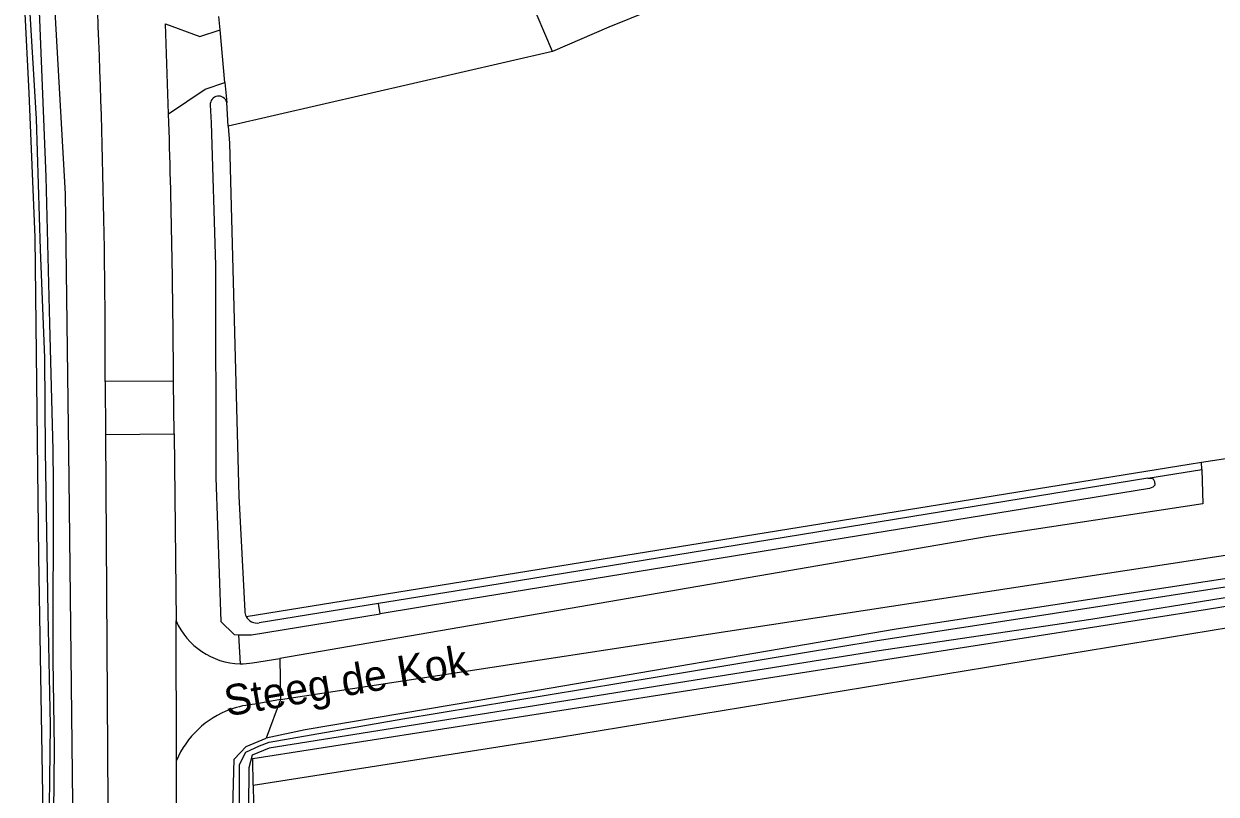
# Model space of a CAD drawing. Extents: x 134297 to 137000, y 403500 to 406000.
# Drawn here: x 135047 to 135144.1, y 403677.8 to 403740.5 of the extents above; entities that cross this region are included whole.
import ezdxf

# ---------------------------------------------------------------- set-up
doc = ezdxf.new("R2010")
doc.units = 0
for name, color, linetype in [('gg-anno-openbare ruimte label', 7, 'Continuous'), ('gg-kntw-bovenkant insteek waterloop', 7, 'Continuous'), ('gg-kntw-waterlijn', 7, 'Continuous'), ('gx-grn-maaiveld', 7, 'Continuous')]:
    doc.layers.add(name, color=color, linetype=linetype)

msp = doc.modelspace()

# ---------------------------------------------------------------- linework, layer by layer
at = {"layer": 'gg-kntw-bovenkant insteek waterloop'}
for points in [[(135171.746, 403699.428), (135118.043, 403691.21), (135085.627, 403685.656), (135069.863, 403683.006), (135066.699, 403682.331)], [(135065.623, 403680.671), (135143.41, 403692.842), (135171.876, 403697.442)]]:
    msp.add_lwpolyline(points, dxfattribs=at)
at = {"layer": 'gg-kntw-waterlijn'}
msp.add_lwpolyline([(135066.934, 403681.993), (135077.838, 403683.899), (135116.331, 403690.244), (135169.319, 403698.436), (135208.319, 403704.818), (135208.686, 403704.046), (135133.896, 403691.995), (135116.465, 403689.408), (135077.663, 403683.211), (135066.933, 403681.511), (135065.545, 403680.928), (135065.288, 403679.91), (135065.185, 403666.72), (135065.306, 403647.731), (135064.91, 403647.731), (135064.537, 403667.991), (135064.537, 403680.178), (135065.038, 403681.176), (135066.154, 403681.705), (135066.934, 403681.993)], dxfattribs=at)
at = {"layer": 'gx-grn-maaiveld'}
for p, q in [((135090.022, 403738.28), (135085.548, 403748.763)), ((135058.749, 403733.177), (135058.487, 403740.522)), ((135062.945, 403740.034), (135062.847, 403741.108)), ((135063.339, 403735.739), (135062.945, 403740.034)), ((135090.022, 403738.28), (135063.611, 403732.174)), ((135063.339, 403735.739), (135063.488, 403734.119)), ((135063.611, 403732.174), (135063.488, 403734.119)), ((135059.15, 403711.396), (135053.591, 403711.368)), ((135053.617, 403707.066), (135059.194, 403707.108)), ((135059.194, 403707.108), (135059.353, 403691.887)), ((135142.922, 403704.807), (135145.947, 403705.283)), ((135142.938, 403704.217), (135142.922, 403704.807)), ((135138.542, 403703.503), (135082.11, 403694.309)), ((135138.542, 403703.503), (135142.938, 403704.217)), ((135067.861, 403685.46), (135171.62, 403701.339)), ((135082.11, 403694.309), (135075.848, 403693.289)), ((135075.848, 403693.289), (135066.119, 403691.704)), ((135075.984, 403692.453), (135075.848, 403693.289)), ((135059.382, 403680.509), (135059.353, 403691.887)), ((135064.454, 403690.751), (135064.573, 403688.384)), ((135065.591, 403688.45), (135067.823, 403688.816)), ((135067.823, 403688.816), (135067.861, 403685.46)), ((135067.861, 403685.46), (135065.805, 403685.094)), ((135067.861, 403685.46), (135066.699, 403682.331)), ((135059.461, 403650.158), (135059.382, 403680.509)), ((135065.642, 403678.482), (135065.623, 403680.671)), ((135065.642, 403678.482), (135065.655, 403677.033))]:
    msp.add_line(p, q, dxfattribs=at)
for points in [[(135117.256, 403749.391), (135094.612, 403740.24), (135090.022, 403738.28)], [(135048.269, 403661.402), (135048.508, 403662.925), (135048.642, 403669.65), (135048.181, 403697.127), (135047.874, 403723.105), (135047.374, 403734.903), (135046.951, 403743.53)], [(135049.344, 403743.941), (135050.32, 403726.679), (135050.621, 403703.438), (135051.004, 403669.814), (135050.927, 403662.756), (135050.536, 403661.631), (135049.892, 403661.131), (135049.321, 403661.012), (135048.538, 403661.138), (135048.269, 403661.402)], [(135048.974, 403672.412), (135049.127, 403683.365), (135048.935, 403692.511), (135048.705, 403705.73), (135048.666, 403713.301), (135048.32, 403722.14), (135047.975, 403732.784), (135047.398, 403742.757), (135047.475, 403743.083), (135047.782, 403743.237), (135048.071, 403743.18), (135048.148, 403742.911), (135048.743, 403728.058), (135049.051, 403716.106), (135049.32, 403705.807), (135049.339, 403703.136), (135049.32, 403688.706)], [(135058.487, 403740.522), (135061.296, 403739.486), (135062.945, 403740.034)], [(135058.749, 403733.177), (135061.732, 403735.205), (135063.339, 403735.739)], [(135062.141, 403733.915), (135062.226, 403732.456), (135062.57, 403720.837), (135062.582, 403703.55), (135063.013, 403691.824), (135064.092, 403690.754), (135064.454, 403690.751)], [(135063.611, 403732.174), (135063.697, 403730.812), (135064.459, 403702.032), (135064.958, 403692.663)], [(135053.591, 403711.368), (135053.591, 403711.364), (135053.591, 403711.361), (135053.617, 403707.066)], [(135059.194, 403707.108), (135059.15, 403711.339), (135059.15, 403711.367), (135059.15, 403711.396)], [(135053.617, 403707.066), (135053.879, 403664.105), (135053.891, 403662.086)], [(135065.069, 403692.232), (135141.918, 403704.649), (135142.922, 403704.807)], [(135065.642, 403678.482), (135090.588, 403682.403), (135213.204, 403702.49), (135212.883, 403704.352)], [(135142.938, 403704.217), (135143.016, 403701.424), (135125.52, 403698.762), (135067.823, 403688.816)], [(135138.542, 403703.503), (135138.812, 403703.505), (135138.982, 403703.451), (135139.091, 403703.242), (135139.098, 403702.935), (135138.947, 403702.775), (135138.678, 403702.667), (135082.246, 403693.473), (135075.984, 403692.453)], [(135064.454, 403690.751), (135065.493, 403690.744), (135075.984, 403692.453)], [(135049.32, 403688.706), (135049.416, 403681.501), (135049.32, 403670.952)], [(135063.771, 403667.214), (135063.964, 403675.584), (135064.08, 403680.621), (135065.055, 403681.64), (135066.699, 403682.331)]]:
    msp.add_lwpolyline(points, dxfattribs=at)
for centre, radius, start, end in [((134325.105, 403711.44), 728.486, 359.994312, 3.032345), ((135062.824, 403733.952), 0.684, 14.09246, 183.13127), ((134217.873, 403706.802), 841.289, 0.312886, 1.796568), ((135064.704, 403694.22), 5.838, 203.55879, 268.71224), ((135065.947, 403692.688), 0.99, 181.4459, 207.43839), ((135065.958, 403692.693), 1.002, 207.37845, 279.22982), ((135064.7, 403694.302), 5.919, 268.76585, 278.65308), ((135066.391, 403677.498), 7.618, 94.41084, 110.09059), ((135066.401, 403677.47), 7.649, 110.08638, 156.58528)]:
    msp.add_arc(centre, radius, start, end, dxfattribs=at)

# ---------------------------------------------------------------- texts
at = {"layer": 'gg-anno-openbare ruimte label'}
msp.add_text('Steeg de Kok', height=2.5, rotation=9.7, dxfattribs=at).set_placement((135063.504, 403684.086))

doc.saveas('drawing.dxf')
